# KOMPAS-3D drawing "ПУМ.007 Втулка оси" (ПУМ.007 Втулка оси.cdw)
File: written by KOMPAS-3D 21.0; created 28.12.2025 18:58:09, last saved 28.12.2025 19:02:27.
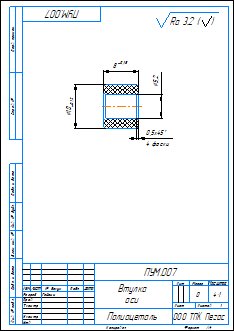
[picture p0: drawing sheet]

Sheet 1: A4, portrait

Document properties: Автор: Гузель; Полное имя файла: C:\Users\Гузель\Desktop\ПУМ\Чертежи\ПУМ.007 Втулка оси.cdw; Знак неуказанной шероховатости: 4; Параметр неуказанной шероховатости: Ra 3.2; Масса: 0.003508

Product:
- Part/product: ПУМ.007 Втулка оси
    Масса: 0.003508

Title block, sheet 1: Наименование: Втулка / оси; designation: ПУМ.007; Материал: Полиацеталь; Масса: 0; Количество листов документа: 1; organisation: ООО ТПК Пегас; Форматы листов документа: A4; Разработал: Гайсин

Views: Вид 1, Местный разрез 1, Спереди
Referenced files in C:\Users\Гузель\Desktop\ПУМ\: ПУМ.007 Втулка оси.m3d
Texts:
  ПУМ.007 Втулка оси
  Ra 3.2
  Ra 3.2 ( )
Dimensions and other numbers on the sheet: 10; 8; 0,5; 4 фаски; 5,2; 4:1; 1; 0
